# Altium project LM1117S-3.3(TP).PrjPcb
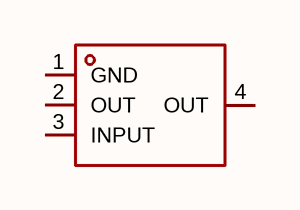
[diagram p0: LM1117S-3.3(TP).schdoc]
1 sheet, 1 parts. Net scope: global (net labels, ports and power ports of the same name join across sheets).

## Sheet LM1117S-3.3(TP).schdoc
size 127 x 101 mm

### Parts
U?  lm1117s-3.3(tp)  [SOT-223-3_L6.5-W3.4-P2.30-LS7.0-BR]  (value not drawn)

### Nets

Not connected (* = marked no-connect by the designer): U? 1(GND) 2(OUT) 3(INPUT) 4(OUT)

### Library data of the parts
U? = lm1117s-3.3(tp): 输出极性:正极;工作电压:18V;输出电压:3.3V;输出电流:1A;输出类型:固定;; Manufacturer: TECH PUBLIC(台舟); AddInBom: yes; ModelId: 925194bf9823436183a3e0b978a8d076; ModelName: SOT-223-4P_L6.5-W3.5-H1.6-LS7.0-P2.30; ModelTransform: 279.89794,255.905,0,180,0,0,-3.9385,-0.0005,0; Output Configuration: 正极; Voltage - Supply: 18V; Output Voltage: 3.3V; Output Current: 1A; standby current: 4mA; Output Type: 固定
